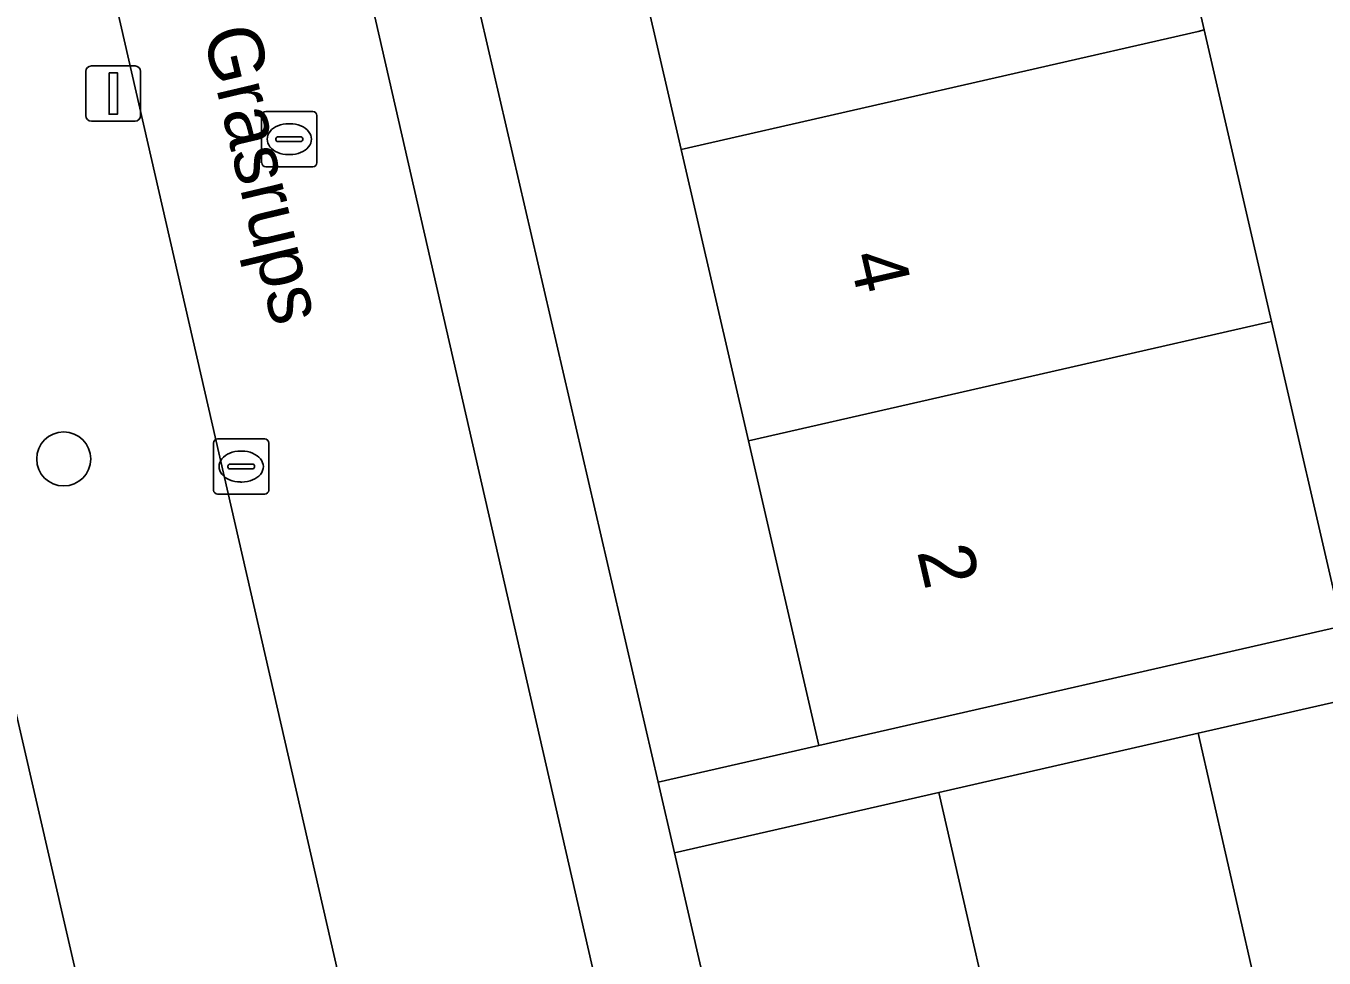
# Model space of a CAD drawing. Extents: x 156412 to 157779, y 382335 to 383768.
# Drawn here: x 157056.03 to 157079.52, y 383050.47 to 383067.34 of the extents above; entities that cross this region are included whole.
import ezdxf

# ---------------------------------------------------------------- set-up
doc = ezdxf.new("R2010")
doc.units = 0
for name, color, linetype in [('IMGEO_Boom', 7, 'Continuous'), ('IMGEO_Erf', 7, 'Continuous'), ('IMGEO_Kolk', 7, 'Continuous'), ('IMGEO_Lichtmast', 7, 'Continuous'), ('IMGEO_Openbare_ruimte_label', 7, 'Continuous'), ('IMGEO_Pand', 7, 'Continuous'), ('IMGEO_Pand_nummerreeks', 7, 'Continuous'), ('IMGEO_Parkeervlak_open', 7, 'Continuous'), ('IMGEO_Rijbaan_lokaal_gesloten', 7, 'Continuous'), ('IMGEO_Rioolput', 7, 'Continuous'), ('IMGEO_Voetpad_open', 7, 'Continuous')]:
    doc.layers.add(name, color=color, linetype=linetype)

msp = doc.modelspace()

# ---------------------------------------------------------------- linework, layer by layer
at = {"layer": 'IMGEO_Boom'}
msp.add_circle((157056.709, 383059.504), 0.489, dxfattribs=at)
at = {"layer": 'IMGEO_Erf'}
for points in [[(157081.536, 383071.716), (157083.485, 383072.166), (157083.048, 383074.056), (157081.1, 383073.606), (157080.321, 383076.978), (157082.27, 383077.428), (157081.833, 383079.318), (157079.884, 383078.868), (157079.108, 383082.229), (157078.615, 383084.365), (157073.664, 383083.227), (157074.917, 383077.801), (157076.136, 383072.524), (157077.35, 383067.268), (157078.569, 383061.991), (157079.843, 383056.475), (157084.79, 383057.602), (157084.289, 383059.8), (157083.518, 383063.14), (157082.77, 383066.377), (157084.718, 383066.827), (157084.264, 383068.795), (157082.315, 383068.345)], [(157066.671, 383070.357), (157065.454, 383075.629), (157064.201, 383081.052), (157061.279, 383080.375), (157067.467, 383053.653), (157070.376, 383054.319), (157069.103, 383059.831), (157067.885, 383065.104)]]:
    msp.add_lwpolyline(points, close=True, dxfattribs=at)
at = {"layer": 'IMGEO_Kolk'}
for p, q in [((157059.42, 383058.94), (157059.42, 383059.792)), ((157059.495, 383059.866), (157060.347, 383059.866)), ((157060.421, 383059.792), (157060.421, 383058.94)), ((157059.908, 383059.646), (157059.933, 383059.646)), ((157059.679, 383059.36), (157059.679, 383059.372)), ((157060.117, 383059.323), (157059.719, 383059.323)), ((157059.722, 383059.409), (157060.12, 383059.409)), ((157060.163, 383059.372), (157060.163, 383059.36)), ((157059.931, 383059.086), (157059.906, 383059.086)), ((157060.347, 383058.866), (157059.495, 383058.866))]:
    msp.add_line(p, q, dxfattribs=at)
for points in [[(157059.42, 383058.94), (157059.42, 383059.792)], [(157059.495, 383059.866), (157060.347, 383059.866)], [(157060.421, 383059.792), (157060.421, 383058.94)], [(157060.347, 383058.866), (157059.495, 383058.866)]]:
    msp.add_lwpolyline(points, dxfattribs=at)
for centre, radius, start, end in [((157059.497, 383059.79), 0.0765, 91.552, 178.448), ((157059.497, 383059.79), 0.0765, 91.552, 178.448), ((157060.345, 383059.79), 0.0765, 1.552, 88.448), ((157060.345, 383059.79), 0.0765, 1.552, 88.448), ((157059.719, 383059.369), 0.0403, 85.8775, 175.7526), ((157059.716, 383059.359), 0.0366, 178.938, 274.7102), ((157060.12, 383059.366), 0.043, 264.8664, 352.4533), ((157060.124, 383059.371), 0.0386, 1.7309, 96.639), ((157059.497, 383058.942), 0.0765, 181.552, 268.448), ((157059.497, 383058.942), 0.0765, 181.552, 268.448), ((157060.345, 383058.942), 0.0765, 271.552, 358.448), ((157060.345, 383058.942), 0.0765, 271.552, 358.448)]:
    msp.add_arc(centre, radius, start, end, dxfattribs=at)
for centre, major_axis, ratio, start_param, end_param in [((157059.907, 383059.366), (-0.387, 0.002), 0.722429, 4.712389, 7.853982), ((157059.932, 383059.366), (-0.39, 0.002), 0.717154, 1.570796, 4.712389)]:
    msp.add_ellipse(centre, major_axis=major_axis, ratio=ratio, start_param=start_param, end_param=end_param, dxfattribs=at)
at = {"layer": 'IMGEO_Lichtmast'}
for p, q in [((157057.21, 383066.618), (157058, 383066.618)), ((157058, 383066.618), (157057.21, 383066.618)), ((157057.11, 383065.718), (157057.11, 383066.518)), ((157057.11, 383066.518), (157057.11, 383065.718)), ((157058.1, 383066.518), (157058.1, 383065.718)), ((157058.1, 383065.718), (157058.1, 383066.518)), ((157058, 383065.618), (157057.21, 383065.618)), ((157057.21, 383065.618), (157058, 383065.618))]:
    msp.add_line(p, q, dxfattribs=at)
msp.add_lwpolyline([(157057.53, 383066.493), (157057.68, 383066.493), (157057.68, 383065.743), (157057.53, 383065.743), (157057.53, 383066.493)], dxfattribs=at)
for centre, start, end in [((157057.21, 383066.518), 90, 180), ((157057.21, 383066.518), 90, 180), ((157058, 383066.518), 0, 90), ((157058, 383066.518), 360, 90), ((157057.21, 383065.718), 180, 270), ((157057.21, 383065.718), 180, 270), ((157058, 383065.718), 270, 0), ((157058, 383065.718), 270, 0)]:
    msp.add_arc(centre, 0.1, start, end, dxfattribs=at)
at = {"layer": 'IMGEO_Pand'}
for points in [[(157076.136, 383072.524), (157076.026, 383072.499), (157066.671, 383070.357), (157067.885, 383065.104), (157077.241, 383067.243), (157077.35, 383067.268)], [(157067.885, 383065.104), (157069.103, 383059.831), (157078.459, 383061.966), (157078.569, 383061.991), (157077.35, 383067.268), (157077.241, 383067.243)], [(157078.569, 383061.991), (157078.459, 383061.966), (157069.103, 383059.831), (157070.376, 383054.319), (157079.843, 383056.475)], [(157081.935, 383055.608), (157077.242, 383054.538), (157079.965, 383042.595), (157079.874, 383042.574), (157080.146, 383041.405), (157083.446, 383042.163), (157083.174, 383043.332), (157084.438, 383043.618), (157084.548, 383043.643), (157084.642, 383043.664)], [(157077.242, 383054.538), (157072.55, 383053.468), (157075.289, 383041.518), (157075.184, 383041.494), (157075.456, 383040.325), (157078.772, 383041.094), (157078.5, 383042.263), (157079.764, 383042.549), (157079.874, 383042.574), (157079.965, 383042.595)], [(157072.55, 383053.468), (157067.762, 383052.377), (157070.787, 383039.253), (157074.082, 383040.014), (157073.81, 383041.183), (157075.074, 383041.469), (157075.184, 383041.494), (157075.289, 383041.518)]]:
    msp.add_lwpolyline(points, close=True, dxfattribs=at)
at = {"layer": 'IMGEO_Parkeervlak_open'}
msp.add_lwpolyline([(157063.89, 383040.486), (157063.199, 383043.56), (157051.788, 383093.312), (157047.229, 383092.303), (157060.035, 383036.721), (157063.984, 383037.622)], dxfattribs=at)
at = {"layer": 'IMGEO_Rijbaan_lokaal_gesloten'}
msp.add_lwpolyline([(157056.19, 383094.365), (157051.788, 383093.312), (157063.199, 383043.56), (157063.89, 383040.486), (157068.295, 383041.495)], close=True, dxfattribs=at)
at = {"layer": 'IMGEO_Rioolput'}
for p, q in [((157060.291, 383064.866), (157060.291, 383065.718)), ((157060.366, 383065.792), (157061.218, 383065.792)), ((157061.292, 383065.718), (157061.292, 383064.866)), ((157060.779, 383065.572), (157060.804, 383065.572)), ((157060.55, 383065.286), (157060.55, 383065.298)), ((157060.988, 383065.249), (157060.59, 383065.249)), ((157060.593, 383065.335), (157060.991, 383065.335)), ((157061.034, 383065.298), (157061.034, 383065.286)), ((157060.802, 383065.012), (157060.777, 383065.012)), ((157061.218, 383064.792), (157060.366, 383064.792))]:
    msp.add_line(p, q, dxfattribs=at)
for points in [[(157060.291, 383064.866), (157060.291, 383065.718)], [(157060.366, 383065.792), (157061.218, 383065.792)], [(157061.292, 383065.718), (157061.292, 383064.866)], [(157061.218, 383064.792), (157060.366, 383064.792)]]:
    msp.add_lwpolyline(points, dxfattribs=at)
for centre, radius, start, end in [((157060.368, 383065.716), 0.0765, 91.552, 178.448), ((157060.368, 383065.716), 0.0765, 91.552, 178.448), ((157061.216, 383065.716), 0.0765, 1.552, 88.448), ((157061.216, 383065.716), 0.0765, 1.552, 88.448), ((157060.59, 383065.295), 0.0403, 85.8775, 175.7526), ((157060.587, 383065.285), 0.0366, 178.938, 274.7102), ((157060.991, 383065.292), 0.043, 264.8664, 352.4533), ((157060.995, 383065.297), 0.0386, 1.7309, 96.639), ((157060.368, 383064.868), 0.0765, 181.552, 268.448), ((157060.368, 383064.868), 0.0765, 181.552, 268.448), ((157061.216, 383064.868), 0.0765, 271.552, 358.448), ((157061.216, 383064.868), 0.0765, 271.552, 358.448)]:
    msp.add_arc(centre, radius, start, end, dxfattribs=at)
for centre, major_axis, ratio, start_param, end_param in [((157060.778, 383065.292), (-0.387, 0.002), 0.722429, 4.712389, 7.853982), ((157060.803, 383065.292), (-0.39, 0.002), 0.717154, 1.570796, 4.712389)]:
    msp.add_ellipse(centre, major_axis=major_axis, ratio=ratio, start_param=start_param, end_param=end_param, dxfattribs=at)
at = {"layer": 'IMGEO_Voetpad_open'}
for points in [[(157061.279, 383080.375), (157060.986, 383081.639), (157057.96, 383094.77), (157056.19, 383094.365), (157068.295, 383041.495), (157068.535, 383040.447), (157069.025, 383038.878), (157070.787, 383039.253), (157067.762, 383052.377), (157067.467, 383053.653)], [(157047.229, 383092.303), (157045.778, 383091.965), (157048.801, 383078.827), (157049.105, 383077.512), (157055.278, 383050.786), (157055.561, 383049.561), (157058.598, 383036.411), (157060.035, 383036.721)]]:
    msp.add_lwpolyline(points, close=True, dxfattribs=at)
msp.add_lwpolyline([(157084.264, 383068.795), (157084.718, 383066.827), (157085.466, 383063.591), (157086.238, 383060.25), (157084.289, 383059.8), (157084.79, 383057.602), (157079.843, 383056.475), (157070.376, 383054.319), (157067.467, 383053.653), (157067.762, 383052.377), (157072.55, 383053.468), (157077.242, 383054.538), (157081.935, 383055.608), (157086.628, 383056.677), (157086.344, 383057.906), (157087.522, 383059.443), (157086.866, 383062.284), (157086.416, 383064.232), (157090.469, 383065.168), (157091.804, 383065.477), (157095.718, 383066.381), (157099.862, 383067.338), (157100.973, 383067.593)], dxfattribs=at)

# ---------------------------------------------------------------- texts
at = {"layer": 'IMGEO_Openbare_ruimte_label'}
msp.add_text('Grasrups', height=1, rotation=283.3553, dxfattribs=at).set_placement((157059.227, 383067.227))
at = {"layer": 'IMGEO_Pand_nummerreeks'}
for s, p in [('4', (157070.917, 383063.175)), ('2', (157072.151, 383057.83))]:
    msp.add_text(s, height=1, rotation=283.0065, dxfattribs=at).set_placement(p)

doc.saveas('drawing.dxf')
